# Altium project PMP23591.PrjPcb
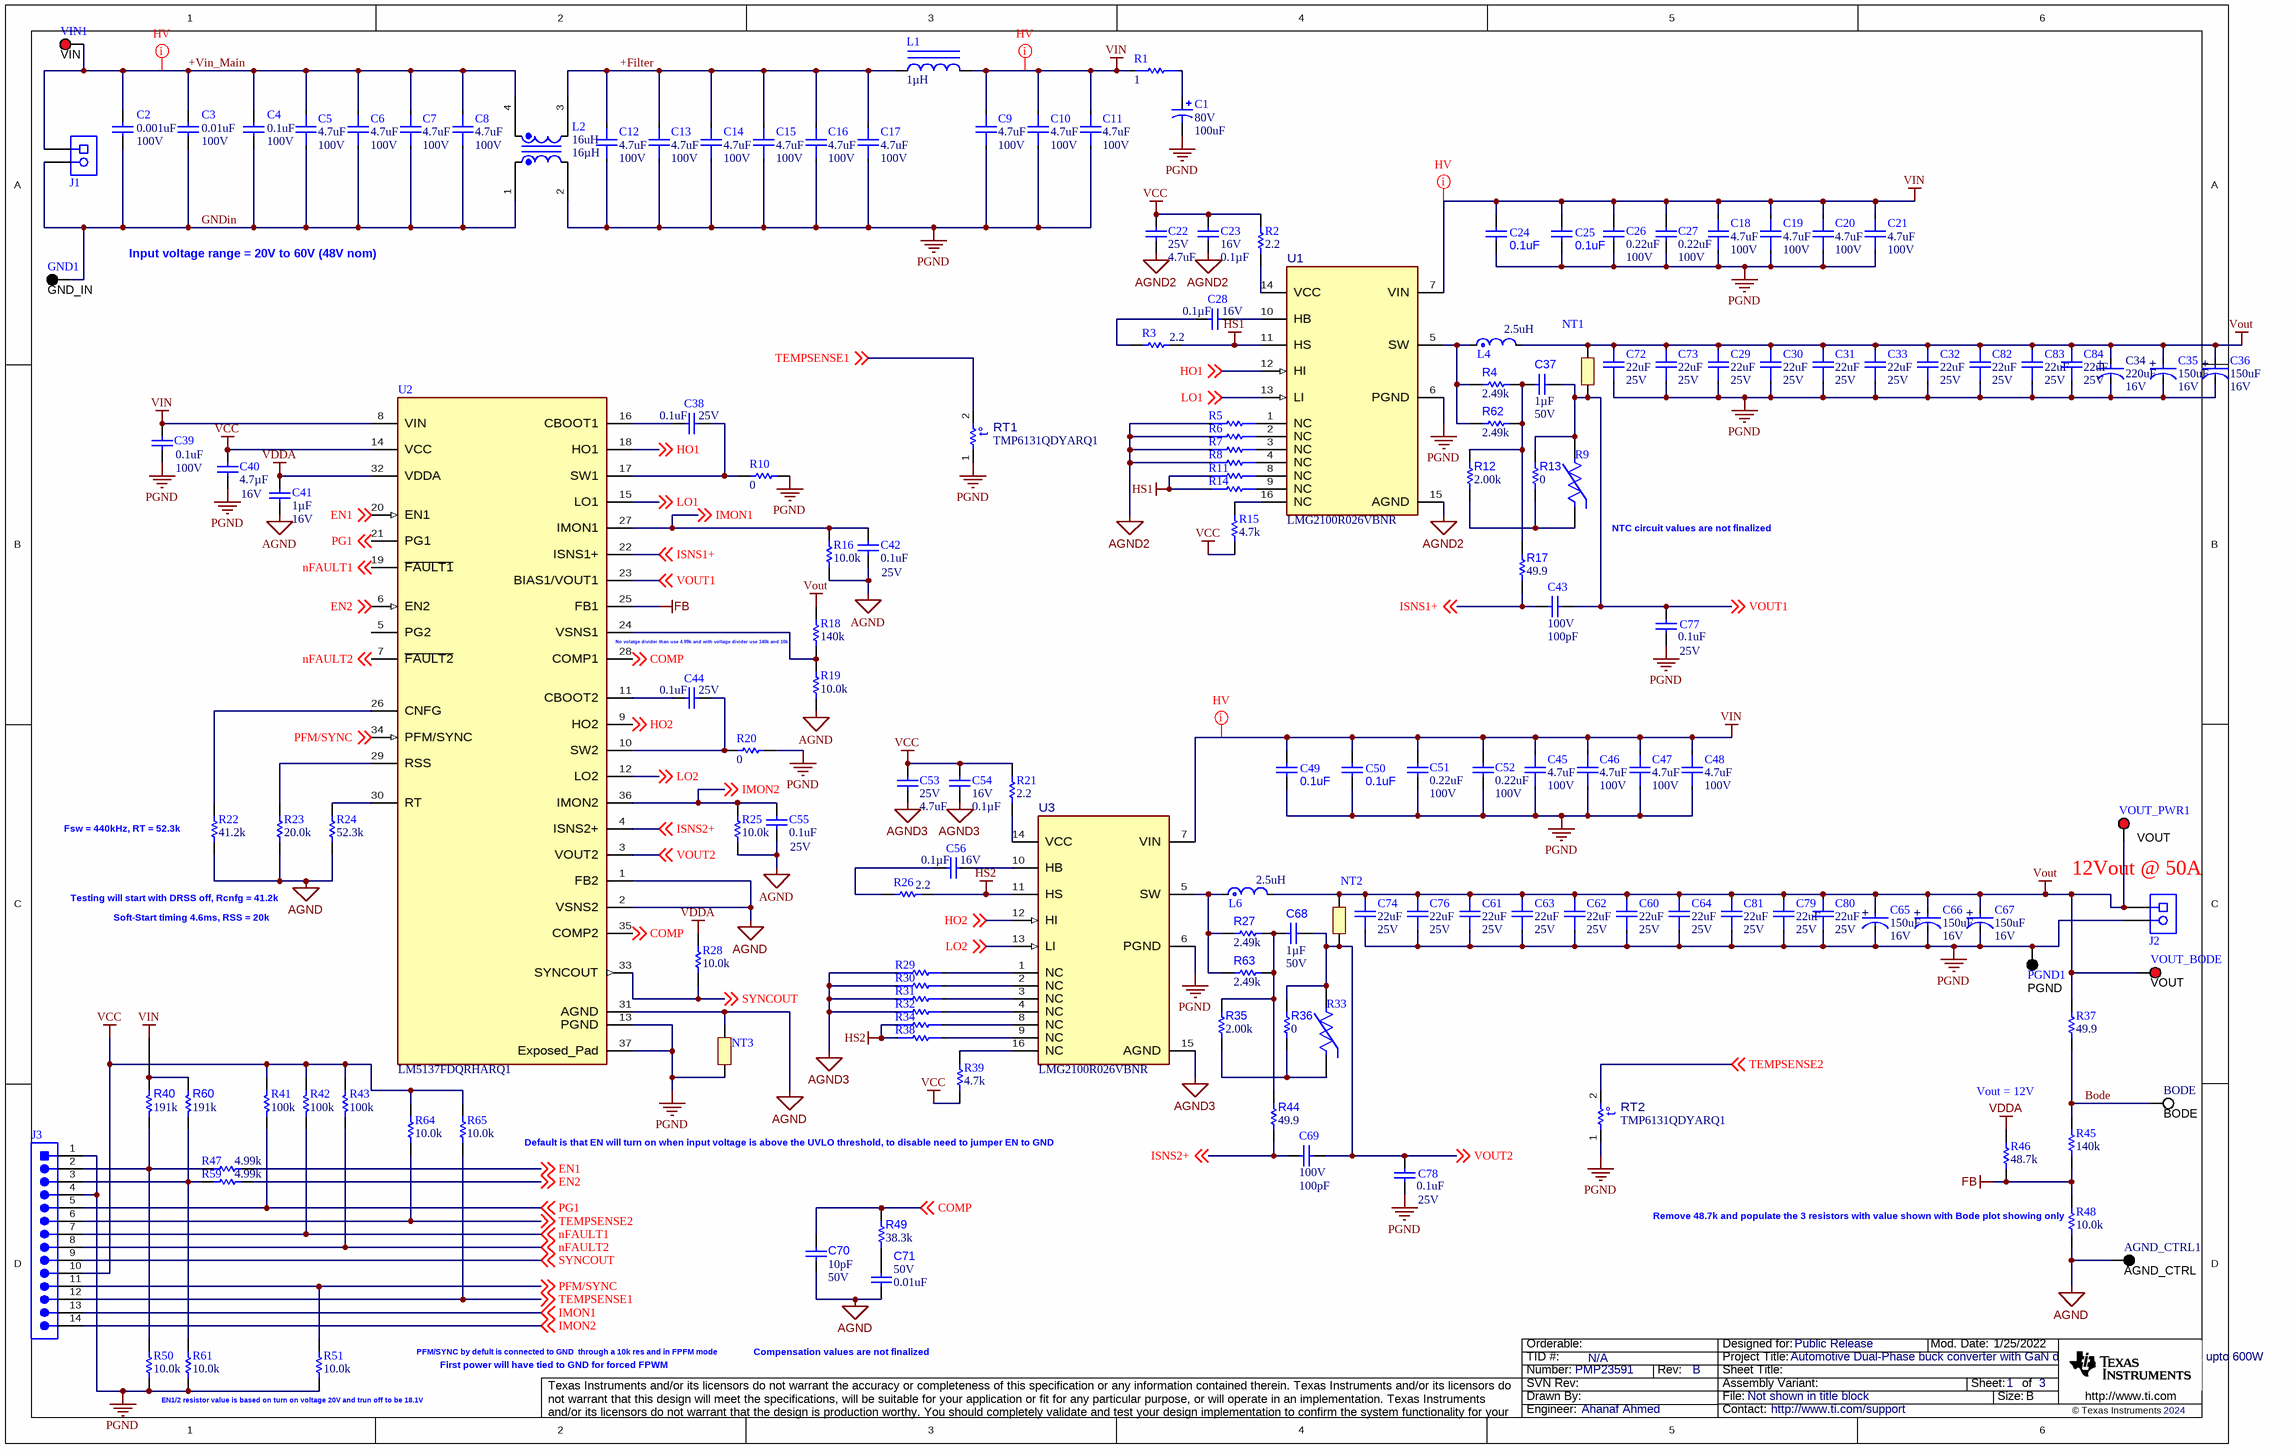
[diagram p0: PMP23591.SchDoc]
CopyrightYear: 2024; PCB_Layout: Ahanaf Ahmed; PCB_Rev: B; PRJ_Customer: Public Release; PRJ_Engineer: Ahanaf Ahmed; PRJ_Number: PMP23591; PRJ_Title: Automotive Dual-Phase buck converter with GaN device 48V input to 12V/50A upto 600W; SCH_Rev: B; TechSupport: http://www.ti.com/support; TID: N/A
3 sheets, 198 parts. Net scope: global (net labels, ports and power ports of the same name join across sheets).
Board file: PMP23591.PcbDoc
Sheets:
  PMP23591.SchDoc
  PMP23591.DynamicLoad.SchDoc
  PMP23591_Hardware.SchDoc

## Sheet PMP23591.SchDoc
size 431 x 279 mm; Date: Not shown in title block; ApprovedBy: Not shown in title block; CheckedBy: Not shown in title block; Author: Not shown in title block; CompanyName: Not shown in title block; Engineer: Not shown in title block; Organization: Not shown in title block; Address1: Not shown in title block; Address2: Not shown in title block; Address3: Not shown in title block; Address4: Not shown in title block; DocumentNumber: 1; Revision: Use project parameter SCH_Rev; SheetNumber: 1; SheetTotal: 3; PageSetup: Record=PageOptions¦CenterHorizontal=True¦CenterVertical=True¦PrintScale=1.00¦XCorrection=1.00¦YCorrection=1.00¦PrintKind=0¦BorderSize=5000000¦LeftOffset=0¦BottomOffset=0¦Orientation=2¦PaperLength=1000¦PaperWidth=1000¦Scale=100¦PaperSource=15¦PrintQuality=600¦MediaType=1¦DitherType=10¦PaperKind=Letter¦PrintScaleMode=1

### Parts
AGND_CTRL1  AGND_CTRL  [Keystone5011]
BODE  BODE  [Keystone5012]
C1  VDC_V: 80V  ValueDisplayed: 100uF  [SM_RADIAL_H13]  (hidden comment: EEV-FK1K101Q)
C2  Cap_F: 0.001uF  VDC_V: 100V  [0603]  (hidden comment: CGA3E2X7R2A102K080AA)
C3  Value2: 100V  ValueDisplayed: 0.01uF  [0603]  (hidden comment: GRM188R72A103KA01D)
C4  Value2: 100V  ValueDisplayed: 0.1uF  [0805]  (hidden comment: C0805C104K1RACTU)
C5  ValueDisplayed: 4.7uF  VDC_V: 100V  [FP-GCJ32DC72A475KE01L_1210-MFG]  (hidden comment: GCJ32DC72A475KE01L)
C6  ValueDisplayed: 4.7uF  VDC_V: 100V  [FP-GCJ32DC72A475KE01L_1210-MFG]  (hidden comment: GCJ32DC72A475KE01L)
C7  ValueDisplayed: 4.7uF  VDC_V: 100V  [FP-GCJ32DC72A475KE01L_1210-MFG]  (hidden comment: GCJ32DC72A475KE01L)
C8  ValueDisplayed: 4.7uF  VDC_V: 100V  [FP-GCJ32DC72A475KE01L_1210-MFG]  (hidden comment: GCJ32DC72A475KE01L)
C9  ValueDisplayed: 4.7uF  VDC_V: 100V  [FP-GCJ32DC72A475KE01L_1210-MFG]  (hidden comment: GCJ32DC72A475KE01L)
C10  ValueDisplayed: 4.7uF  VDC_V: 100V  [FP-GCJ32DC72A475KE01L_1210-MFG]  (hidden comment: GCJ32DC72A475KE01L)
C11  ValueDisplayed: 4.7uF  VDC_V: 100V  [FP-GCJ32DC72A475KE01L_1210-MFG]  (hidden comment: GCJ32DC72A475KE01L)
C12  ValueDisplayed: 4.7uF  VDC_V: 100V  [FP-GCJ32DC72A475KE01L_1210-MFG]  (hidden comment: GCJ32DC72A475KE01L)
C13  ValueDisplayed: 4.7uF  VDC_V: 100V  [FP-GCJ32DC72A475KE01L_1210-MFG]  (hidden comment: GCJ32DC72A475KE01L)
C14  ValueDisplayed: 4.7uF  VDC_V: 100V  [FP-GCJ32DC72A475KE01L_1210-MFG]  (hidden comment: GCJ32DC72A475KE01L)
C15  ValueDisplayed: 4.7uF  VDC_V: 100V  [FP-GCJ32DC72A475KE01L_1210-MFG]  (hidden comment: GCJ32DC72A475KE01L)
C16  ValueDisplayed: 4.7uF  VDC_V: 100V  [FP-GCJ32DC72A475KE01L_1210-MFG]  (hidden comment: GCJ32DC72A475KE01L)
C17  ValueDisplayed: 4.7uF  VDC_V: 100V  [FP-GCJ32DC72A475KE01L_1210-MFG]  (hidden comment: GCJ32DC72A475KE01L)
C18  ValueDisplayed: 4.7uF  VDC_V: 100V  [FP-GCJ32DC72A475KE01L_1210-MFG]  (hidden comment: GCJ32DC72A475KE01L)
C19  ValueDisplayed: 4.7uF  VDC_V: 100V  [FP-GCJ32DC72A475KE01L_1210-MFG]  (hidden comment: GCJ32DC72A475KE01L)
C20  ValueDisplayed: 4.7uF  VDC_V: 100V  [FP-GCJ32DC72A475KE01L_1210-MFG]  (hidden comment: GCJ32DC72A475KE01L)
C21  ValueDisplayed: 4.7uF  VDC_V: 100V  [FP-GCJ32DC72A475KE01L_1210-MFG]  (hidden comment: GCJ32DC72A475KE01L)
C22  VDC_V: 25V  ValueDisplayed: 4.7uF  [0805_HV]  (hidden comment: GCM21BC71E475KE36L)
C23  VDC_V: 16V  ValueDisplayed: 0.1µF  [0402]  (hidden comment: GCM155R71C104JA55D)
C24  ValueDisplayed: 0.1uF  [0603]  (hidden comment: CGA3E2X7R1E104K080AA)
C25  ValueDisplayed: 0.1uF  [0603]  (hidden comment: CGA3E2X7R1E104K080AA)
C26  Cap_F: 0.22uF  VDC_V: 100V  [0805]  (hidden comment: CL21B224KCFSNWE)
C27  Cap_F: 0.22uF  VDC_V: 100V  [0805]  (hidden comment: CL21B224KCFSNWE)
C28  VDC_V: 16V  ValueDisplayed: 0.1µF  [0402]  (hidden comment: GCM155R71C104JA55D)
C29  ValueDisplayed: 22uF  VDC_V: 25V  [FP-CGA6P3X7R1E226M250AB_1210-MFG]  (hidden comment: CGA6P3X7R1E226M250AB)
C30  ValueDisplayed: 22uF  VDC_V: 25V  [FP-CGA6P3X7R1E226M250AB_1210-MFG]  (hidden comment: CGA6P3X7R1E226M250AB)
C31  ValueDisplayed: 22uF  VDC_V: 25V  [FP-CGA6P3X7R1E226M250AB_1210-MFG]  (hidden comment: CGA6P3X7R1E226M250AB)
C32  ValueDisplayed: 22uF  VDC_V: 25V  [FP-CGA6P3X7R1E226M250AB_1210-MFG]  (hidden comment: CGA6P3X7R1E226M250AB)
C33  ValueDisplayed: 22uF  VDC_V: 25V  [FP-CGA6P3X7R1E226M250AB_1210-MFG]  (hidden comment: CGA6P3X7R1E226M250AB)
C34  ValueDisplayed: 220uF  VDC_V: 16V  [FP-TCME227M016R0025E_2917-MFG]  (hidden comment: TCME227M016R0025E)
C35  ValueDisplayed: 150uF  VDC_V: 16V  [FP-TCQE157M016R0025E_2917-MFG]  (hidden comment: TCQE157M016R0025E)
C36  ValueDisplayed: 150uF  VDC_V: 16V  [FP-TCQE157M016R0025E_2917-MFG]  (hidden comment: TCQE157M016R0025E)
C37  Cap_F: 1µF  VDC_V: 50V  [0603]  (hidden comment: UMK107AB7105KA-T)
C38  Value2: 25V  ValueDisplayed: 0.1uF  [0603]  (hidden comment: CGA3E2X7R1E104K080AA)
C39  Value2: 100V  ValueDisplayed: 0.1uF  [0603]  (hidden comment: GRM188R72A104KA35D)
C40  Value2: 16V  Cap_F: 4.7µF  [0603]  (hidden comment: GRM188Z71C475KE21D)
C41  Cap_F: 1µF  VDC_V: 16V  [0603L]  (hidden comment: GCM188R71C105KA64J)
C42  Value2: 25V  ValueDisplayed: 0.1uF  [0603]  (hidden comment: CGA3E2X7R1E104K080AA)
C43  VDC_V: 100V  ValueDisplayed: 100pF  [0603]  (hidden comment: GCM1885C2A101JA16D)
C44  Value2: 25V  ValueDisplayed: 0.1uF  [0603]  (hidden comment: CGA3E2X7R1E104K080AA)
C45  ValueDisplayed: 4.7uF  VDC_V: 100V  [FP-GCJ32DC72A475KE01L_1210-MFG]  (hidden comment: GCJ32DC72A475KE01L)
C46  ValueDisplayed: 4.7uF  VDC_V: 100V  [FP-GCJ32DC72A475KE01L_1210-MFG]  (hidden comment: GCJ32DC72A475KE01L)
C47  ValueDisplayed: 4.7uF  VDC_V: 100V  [FP-GCJ32DC72A475KE01L_1210-MFG]  (hidden comment: GCJ32DC72A475KE01L)
C48  ValueDisplayed: 4.7uF  VDC_V: 100V  [FP-GCJ32DC72A475KE01L_1210-MFG]  (hidden comment: GCJ32DC72A475KE01L)
C49  ValueDisplayed: 0.1uF  [0603]  (hidden comment: CGA3E2X7R1E104K080AA)
C50  ValueDisplayed: 0.1uF  [0603]  (hidden comment: CGA3E2X7R1E104K080AA)
C51  Cap_F: 0.22uF  VDC_V: 100V  [0805]  (hidden comment: CL21B224KCFSNWE)
C52  Cap_F: 0.22uF  VDC_V: 100V  [0805]  (hidden comment: CL21B224KCFSNWE)
C53  VDC_V: 25V  ValueDisplayed: 4.7uF  [0805_HV]  (hidden comment: GCM21BC71E475KE36L)
C54  VDC_V: 16V  ValueDisplayed: 0.1µF  [0402]  (hidden comment: GCM155R71C104JA55D)
C55  Value2: 25V  ValueDisplayed: 0.1uF  [0603]  (hidden comment: CGA3E2X7R1E104K080AA)
C56  VDC_V: 16V  ValueDisplayed: 0.1µF  [0402]  (hidden comment: GCM155R71C104JA55D)
C60  ValueDisplayed: 22uF  VDC_V: 25V  [FP-CGA6P3X7R1E226M250AB_1210-MFG]  (hidden comment: CGA6P3X7R1E226M250AB)
C61  ValueDisplayed: 22uF  VDC_V: 25V  [FP-CGA6P3X7R1E226M250AB_1210-MFG]  (hidden comment: CGA6P3X7R1E226M250AB)
C62  ValueDisplayed: 22uF  VDC_V: 25V  [FP-CGA6P3X7R1E226M250AB_1210-MFG]  (hidden comment: CGA6P3X7R1E226M250AB)
C63  ValueDisplayed: 22uF  VDC_V: 25V  [FP-CGA6P3X7R1E226M250AB_1210-MFG]  (hidden comment: CGA6P3X7R1E226M250AB)
C64  ValueDisplayed: 22uF  VDC_V: 25V  [FP-CGA6P3X7R1E226M250AB_1210-MFG]  (hidden comment: CGA6P3X7R1E226M250AB)
C65  ValueDisplayed: 150uF  VDC_V: 16V  [FP-TCQE157M016R0025E_2917-MFG]  (hidden comment: TCQE157M016R0025E)
C66  ValueDisplayed: 150uF  VDC_V: 16V  [FP-TCQE157M016R0025E_2917-MFG]  (hidden comment: TCQE157M016R0025E)
C67  ValueDisplayed: 150uF  VDC_V: 16V  [FP-TCQE157M016R0025E_2917-MFG]  (hidden comment: TCQE157M016R0025E)
C68  Cap_F: 1µF  VDC_V: 50V  [0603]  (hidden comment: UMK107AB7105KA-T)
C69  VDC_V: 100V  ValueDisplayed: 100pF  [0603]  (hidden comment: GCM1885C2A101JA16D)
C70  ValueDisplayed: 10pF  VDC_V: 50V  [0603]  (hidden comment: CGA3E2C0G1H100D080AA)
C71  VDC_V: 50V  ValueDisplayed: 0.01uF  [0603]  (hidden comment: GCM188R71H103KA37D)
C72  ValueDisplayed: 22uF  VDC_V: 25V  [FP-CGA6P3X7R1E226M250AB_1210-MFG]  (hidden comment: CGA6P3X7R1E226M250AB)
C73  ValueDisplayed: 22uF  VDC_V: 25V  [FP-CGA6P3X7R1E226M250AB_1210-MFG]  (hidden comment: CGA6P3X7R1E226M250AB)
C74  ValueDisplayed: 22uF  VDC_V: 25V  [FP-CGA6P3X7R1E226M250AB_1210-MFG]  (hidden comment: CGA6P3X7R1E226M250AB)
C76  ValueDisplayed: 22uF  VDC_V: 25V  [FP-CGA6P3X7R1E226M250AB_1210-MFG]  (hidden comment: CGA6P3X7R1E226M250AB)
C77  Value2: 25V  ValueDisplayed: 0.1uF  [0603]  (hidden comment: CGA3E2X7R1E104K080AA)
C78  Value2: 25V  ValueDisplayed: 0.1uF  [0603]  (hidden comment: CGA3E2X7R1E104K080AA)
C79  ValueDisplayed: 22uF  VDC_V: 25V  [FP-CGA6P3X7R1E226M250AB_1210-MFG]  (hidden comment: CGA6P3X7R1E226M250AB)
C80  ValueDisplayed: 22uF  VDC_V: 25V  [FP-CGA6P3X7R1E226M250AB_1210-MFG]  (hidden comment: CGA6P3X7R1E226M250AB)
C81  ValueDisplayed: 22uF  VDC_V: 25V  [FP-CGA6P3X7R1E226M250AB_1210-MFG]  (hidden comment: CGA6P3X7R1E226M250AB)
C82  ValueDisplayed: 22uF  VDC_V: 25V  [FP-CGA6P3X7R1E226M250AB_1210-MFG]  (hidden comment: CGA6P3X7R1E226M250AB)
C83  ValueDisplayed: 22uF  VDC_V: 25V  [FP-CGA6P3X7R1E226M250AB_1210-MFG]  (hidden comment: CGA6P3X7R1E226M250AB)
C84  ValueDisplayed: 22uF  VDC_V: 25V  [FP-CGA6P3X7R1E226M250AB_1210-MFG]  (hidden comment: CGA6P3X7R1E226M250AB)
GND1  GND_IN  [Keystone5011]
J1  EM292902-UL  [Eaton_EM292902]  (value not drawn)
J2  EM292902-UL  [Eaton_EM292902]  (value not drawn)
J3  TSW-114-07-G-S  [TSW-114-07-G-S]  (value not drawn)
L1  ValueDisplayed: 1µH  [VCHA105D]  (hidden comment: VCHA105D-1R0MS6)
L2  value 16uH  ValueDisplayed: 16µH  [WE-CMB_NiZn_S]  (hidden comment: 7448421016)
L4  value 2.5uH  [FP-VCUD128T-2R5MS8_SMT_IND_13MM3_12MM8-MFG]  (hidden comment: VCUD128T-2R5MS8)
L6  value 2.5uH  [FP-VCUD128T-2R5MS8_SMT_IND_13MM3_12MM8-MFG]
NT1  Net-Tie  [Net-Tie_10mil]  (value not drawn)  (net tie, no BOM)
NT2  Net-Tie  [Net-Tie_10mil]  (value not drawn)  (net tie, no BOM)
NT3  Net-Tie  [Net-Tie_10mil]  (value not drawn)  (net tie, no BOM)
PGND1  PGND  [Keystone5011]
R1  value 1  [FP-RCL12251R00FKEG_2512-MFG]  (hidden comment: RCL12251R00FKEG)
R2  ValueDisplayed: 2.2  [0402]  (hidden comment: CRCW04022R20JNED)
R3  ValueDisplayed: 2.2  [0402]  (hidden comment: CRCW04022R20JNED)
R4  ValueDisplayed: 2.49k  [1210]  (hidden comment: RC1210FR-072K49L)
R5  CRCW06030000Z0EAHP  [FP-CRCW06030000Z0EAHP_0603-MFG]  (value not drawn)
R6  CRCW06030000Z0EAHP  [FP-CRCW06030000Z0EAHP_0603-MFG]  (value not drawn)
R7  CRCW06030000Z0EAHP  [FP-CRCW06030000Z0EAHP_0603-MFG]  (value not drawn)
R8  CRCW06030000Z0EAHP  [FP-CRCW06030000Z0EAHP_0603-MFG]  (value not drawn)
R9  NCU18WB473J6SRB  [FP-NCU18WB473J6SRB_0603-MFG]  (value not drawn)
R10  ValueDisplayed: 0  [0603]  (hidden comment: CRCW06030000Z0EA)
R11  CRCW06030000Z0EAHP  [FP-CRCW06030000Z0EAHP_0603-MFG]  (value not drawn)
R12  ValueDisplayed: 2.00k  [0603]  (hidden comment: CRCW06032K00FKEA)
R13  ValueDisplayed: 0  [0603]  (hidden comment: RCS06030000Z0EA)
R14  CRCW06030000Z0EAHP  [FP-CRCW06030000Z0EAHP_0603-MFG]  (value not drawn)
R15  ValueDisplayed: 4.7k  [0603]  (hidden comment: CRCW06034K70JNEA)
R16  ValueDisplayed: 10.0k  [0603]  (hidden comment: CRCW060310K0FKEA)
R17  ValueDisplayed: 49.9  [0603]  (hidden comment: ERJ-3EKF49R9V)
R18  ValueDisplayed: 140k  [0603]  (hidden comment: ERA-3AEB1403V)
R19  ValueDisplayed: 10.0k  [0603L]  (hidden comment: CRCW060310K0FKEA)
R20  ValueDisplayed: 0  [0603]  (hidden comment: CRCW06030000Z0EA)
R21  ValueDisplayed: 2.2  [0402]  (hidden comment: CRCW04022R20JNED)
R22  ValueDisplayed: 41.2k  [0603]  (hidden comment: CRCW060341K2FKEA)
R23  ValueDisplayed: 20.0k  [0603S]  (hidden comment: CRCW060320K0FKEA)
R24  ValueDisplayed: 52.3k  [0603L]  (hidden comment: CRCW060352K3FKEA)
R25  ValueDisplayed: 10.0k  [0603]  (hidden comment: CRCW060310K0FKEA)
R26  ValueDisplayed: 2.2  [0402]  (hidden comment: CRCW04022R20JNED)
R27  ValueDisplayed: 2.49k  [1210]  (hidden comment: RC1210FR-072K49L)
R28  ValueDisplayed: 10.0k  [0603]  (hidden comment: CRCW060310K0FKEA)
R29  CRCW06030000Z0EAHP  [FP-CRCW06030000Z0EAHP_0603-MFG]  (value not drawn)
R30  CRCW06030000Z0EAHP  [FP-CRCW06030000Z0EAHP_0603-MFG]  (value not drawn)
R31  CRCW06030000Z0EAHP  [FP-CRCW06030000Z0EAHP_0603-MFG]  (value not drawn)
R32  CRCW06030000Z0EAHP  [FP-CRCW06030000Z0EAHP_0603-MFG]  (value not drawn)
R33  NCU18WB473J6SRB  [FP-NCU18WB473J6SRB_0603-MFG]  (value not drawn)
R34  CRCW06030000Z0EAHP  [FP-CRCW06030000Z0EAHP_0603-MFG]  (value not drawn)
R35  ValueDisplayed: 2.00k  [0603]  (hidden comment: CRCW06032K00FKEA)
R36  ValueDisplayed: 0  [0603]  (hidden comment: RCS06030000Z0EA)
R37  ValueDisplayed: 49.9  [0603L]  (hidden comment: CRCW060349R9FKEA)
R38  CRCW06030000Z0EAHP  [FP-CRCW06030000Z0EAHP_0603-MFG]  (value not drawn)
R39  ValueDisplayed: 4.7k  [0603]  (hidden comment: CRCW06034K70JNEA)
R40  ValueDisplayed: 191k  [0603]  (hidden comment: CRCW0603191KFKEA)
R41  ValueDisplayed: 100k  [0603L]  (hidden comment: CRCW0603100KFKEA)
R42  ValueDisplayed: 100k  [0603L]  (hidden comment: CRCW0603100KFKEA)
R43  ValueDisplayed: 100k  [0603L]  (hidden comment: CRCW0603100KFKEA)
R44  ValueDisplayed: 49.9  [0603]  (hidden comment: ERJ-3EKF49R9V)
R45  ValueDisplayed: 140k  [0603]  (hidden comment: ERA-3AEB1403V)
R46  ValueDisplayed: 48.7k  [0603]  (hidden comment: CRCW060348K7FKEA)
R47  ValueDisplayed: 4.99k  [0603]  (hidden comment: CRCW06034K99FKEA)
R48  ValueDisplayed: 10.0k  [0603L]  (hidden comment: CRCW060310K0FKEA)
R49  ValueDisplayed: 38.3k  [0603]  (hidden comment: CRCW060338K3FKEA)
R50  ValueDisplayed: 10.0k  [0603]  (hidden comment: CRCW060310K0FKEA)
R51  ValueDisplayed: 10.0k  [0603]  (hidden comment: CRCW060310K0FKEA)
R59  ValueDisplayed: 4.99k  [0603]  (hidden comment: CRCW06034K99FKEA)
R60  ValueDisplayed: 191k  [0603]  (hidden comment: CRCW0603191KFKEA)
R61  ValueDisplayed: 10.0k  [0603]  (hidden comment: CRCW060310K0FKEA)
R62  ValueDisplayed: 2.49k  [1210]  (hidden comment: RC1210FR-072K49L)
R63  ValueDisplayed: 2.49k  [1210]  (hidden comment: RC1210FR-072K49L)
R64  ValueDisplayed: 10.0k  [0603]  (hidden comment: CRCW060310K0FKEA)
R65  ValueDisplayed: 10.0k  [0603]  (hidden comment: CRCW060310K0FKEA)
RT1  TMP6131QDYARQ1  [DYA0002A-MFG]
RT2  TMP6131QDYARQ1  [DYA0002A-MFG]
U1  LMG2100R026VBNR  [VBN0016A-MFG]
U2  LM5137FDQRHARQ1  [RHA0036D-MFG]
U3  LMG2100R026VBNR  [VBN0016A-MFG]
VIN1  VIN  [Keystone5010]
VOUT_BODE  VOUT  [Keystone5010]
VOUT_PWR1  VOUT  [Keystone5010]

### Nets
AGND: AGND_CTRL1.1 C41.1 C42.1 C55.1 C70.2 C71.2 NT3.2 R16.2 R19.2 R22.1 R23.1 R24.1 R25.2 R48.2 U2.1(FB2) U2.2(VSNS2) U2.31(AGND)
AGND2: C22.2 C23.2 R5.1 R6.1 R7.1 R8.1 U1.15(AGND)
AGND3: C53.2 C54.2 R29.1 R30.1 R31.1 R32.1 U3.15(AGND)
FB: R45.1 R46.1 R48.1 U2.25(FB1)
HS1: R3.1 R11.1 R14.1 U1.11(HS)
HS2: R26.1 R34.1 R38.1 U3.11(HS)
PGND: C1.2(-) C9.1 C10.1 C11.1 C12.1 C13.1 C14.1 C15.1 C16.1 C17.1 C18.1 C19.1 C20.1 C21.1 C24.1 C25.1 C26.2 C27.2 C29.1 C30.1 C31.1 C32.1 C33.1 C34.1(CATHODE) C35.1(CATHODE) C36.1(CATHODE) C39.2 C40.2 C45.1 C46.1 C47.1 C48.1 C49.1 C50.1 C51.2 C52.2 C60.1 C61.1 C62.1 C63.1 C64.1 C65.1(CATHODE) C66.1(CATHODE) C67.1(CATHODE) C72.1 C73.1 C74.1 C76.1 C77.1 C78.1 C79.1 C80.1 C81.1 C82.1 C83.1 C84.1 J2.2 J3.1 J3.4 L2.2 NT3.1 PGND1.1 R10.2 R20.2 R50.2 R51.2 R61.2 RT1.1 RT2.1 U1.6(PGND) U2.13(PGND) U2.37(Exposed_Pad) U3.6(PGND)
VCC: C22.1 C23.1 C40.1 C53.1 C54.1 J3.10 R2.1 R15.2 R21.1 R39.2 R41.2 R42.2 R43.2 R64.1 R65.1 U2.14(VCC)
VDDA: C41.2 R28.1 R46.2 U2.32(VDDA)
VIN: C9.2 C10.2 C11.2 C18.2 C19.2 C20.2 C21.2 C24.2 C25.2 C26.1 C27.1 C39.1 C45.2 C46.2 C47.2 C48.2 C49.2 C50.2 C51.1 C52.1 L1.2 R1.2 R40.2 R60.2 U1.7(VIN) U2.8(VIN) U3.7(VIN)
Vout: C29.2 C30.2 C31.2 C32.2 C33.2 C34.2(ANODE) C35.2(ANODE) C36.2(ANODE) C60.2 C61.2 C62.2 C63.2 C64.2 C65.2(ANODE) C66.2(ANODE) C67.2(ANODE) C72.2 C73.2 C74.2 C76.2 C79.2 C80.2 C81.2 C82.2 C83.2 C84.2 J2.1 L4.2 L6.2 NT1.2 NT2.2 R18.2 R37.2 VOUT_BODE.1 VOUT_PWR1.1
+Filter: C12.2 C13.2 C14.2 C15.2 C16.2 C17.2 L1.1 L2.3
+Vin_Main: C2.1 C3.2 C4.1 C5.2 C6.2 C7.2 C8.2 J1.1 L2.4 VIN1.1
Bode: BODE.1 R37.1 R45.2
COMP: C70.1 R49.2 U2.28(COMP1) U2.35(COMP2) ; off-sheet COMP
EN1: R47.2 U2.20(EN1) ; off-sheet EN1
EN2: R59.2 U2.6(EN2) ; off-sheet EN2
GNDin: C2.2 C3.1 C4.2 C5.1 C6.1 C7.1 C8.1 GND1.1 J1.2 L2.1
HO1: U1.12(HI) U2.18(HO1) ; off-sheet HO1
HO2: U2.9(HO2) U3.12(HI) ; off-sheet HO2
IMON1: C42.2 J3.13 R16.1 U2.27(IMON1) ; off-sheet IMON1
IMON2: C55.2 J3.14 R25.1 U2.36(IMON2) ; off-sheet IMON2
ISNS1+: C43.2 R17.1 U2.22(ISNS1+) ; off-sheet ISNS1+
ISNS2+: C69.2 R44.1 U2.4(ISNS2+) ; off-sheet ISNS2+
LO1: U1.13(LI) U2.15(LO1) ; off-sheet LO1
LO2: U2.12(LO2) U3.13(LI) ; off-sheet LO2
nFAULT1: J3.7 R42.1 U2.19(~{FAULT1}) ; off-sheet nFAULT1
nFAULT2: J3.8 R43.1 U2.7(~{FAULT2}) ; off-sheet nFAULT2
PFM/SYNC: J3.11 R51.1 U2.34(PFM/SYNC) ; off-sheet PFM/SYNC
PG1: J3.5 R41.1 U2.21(PG1) ; off-sheet PG1
SYNCOUT: J3.9 R28.2 U2.33(SYNCOUT) ; off-sheet SYNCOUT
TEMPSENSE1: J3.12 R65.2 RT1.2 ; off-sheet TEMPSENSE1
TEMPSENSE2: J3.6 R64.2 RT2.2 ; off-sheet TEMPSENSE2
VOUT1: C37.1 C43.1 C77.2 NT1.1 R9.2 R13.2 U2.23(BIAS1/VOUT1) ; off-sheet VOUT1
VOUT2: C68.1 C69.1 C78.2 NT2.1 R33.2 R36.2 U2.3(VOUT2) ; off-sheet VOUT2
NetC1_1: C1.1(+) R1.1
NetC28_1: C28.1 R3.2
NetC28_2: C28.2 U1.10(HB)
NetC37_2: C37.2 R4.2 R12.2 R17.2 R62.2
NetC38_1: C38.1 R10.1 U2.17(SW1)
NetC38_2: C38.2 U2.16(CBOOT1)
NetC44_1: C44.1 R20.1 U2.10(SW2)
NetC44_2: C44.2 U2.11(CBOOT2)
NetC56_1: C56.1 R26.2
NetC56_2: C56.2 U3.10(HB)
NetC68_2: C68.2 R27.2 R35.2 R44.2 R63.2
NetC71_1: C71.1 R49.1
NetJ3_2: J3.2 R40.1 R47.1 R50.1
NetJ3_3: J3.3 R59.1 R60.1 R61.1
NetL4_1: L4.1 R4.1 R62.1 U1.5(SW)
NetL6_1: L6.1 R27.1 R63.1 U3.5(SW)
NetR2_2: R2.2 U1.14(VCC)
NetR5_2: R5.2 U1.1(NC)
NetR6_2: R6.2 U1.2(NC)
NetR7_2: R7.2 U1.3(NC)
NetR8_2: R8.2 U1.4(NC)
NetR9_1: R9.1 R12.1 R13.1
NetR11_2: R11.2 U1.8(NC)
NetR14_2: R14.2 U1.9(NC)
NetR15_1: R15.1 U1.16(NC)
NetR18_1: R18.1 R19.1 U2.24(VSNS1)
NetR21_2: R21.2 U3.14(VCC)
NetR22_2: R22.2 U2.26(CNFG)
NetR23_2: R23.2 U2.29(RSS)
NetR24_2: R24.2 U2.30(RT)
NetR29_2: R29.2 U3.1(NC)
NetR30_2: R30.2 U3.2(NC)
NetR31_2: R31.2 U3.3(NC)
NetR32_2: R32.2 U3.4(NC)
NetR33_1: R33.1 R35.1 R36.1
NetR34_2: R34.2 U3.8(NC)
NetR38_2: R38.2 U3.9(NC)
NetR39_1: R39.1 U3.16(NC)

Not connected (* = marked no-connect by the designer): U2 5(PG2)

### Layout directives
net class HV: +Vin_Main, VIN

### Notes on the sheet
- Input voltage range = 20V to 60V (48V nom)
- (near R9) NTC circuit values are not finalized
- (near U2) No volatge divider than use 4.99k and with voltage divider use 140k and 10k
- (near R22) Fsw = 440kHz, RT = 52.3k
- 12Vout @ 50A
- Testing will start with DRSS off, Rcnfg = 41.2k
- Soft-Start timing 4.6ms, RSS = 20k
- Default is that EN will turn on when input voltage is above the UVLO threshold, to disable need to jumper EN to GND
- Vout = 12V
- (near R48) Remove 48.7k and populate the 3 resistors with value shown with Bode plot showing only
- EN1/2 resistor value is based on turn on voltage 20V and trun off to be 18.1V
- First power will have tied to GND for forced FPWM
- PFM/SYNC by defult is connected to GND  through a 10k res and in FPFM mode
- Compensation values are not finalized

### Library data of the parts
AGND_CTRL1 = CMP-0055148-2: Test Point, Multipurpose, Black, TH; Manufacturer: Keystone Electronics; CNHeader: FALSE; ContactFinish: Silver; Green_REACh: Passed; Green_Lifecycle: Active; CT: TRUE
BODE = CMP-0055149-2: Test Point, Multipurpose, White, TH; Manufacturer: Keystone Electronics; ContactFinish: Silver; CT: TRUE; CNHeader: FALSE; Green_Lifecycle: Active; Green_REACh: Passed
C1 = CMP-0011216-2: CAP, AL, 100 uF, 80 V, +/- 20%, 0.32 ohm, AEC-Q200 Grade 2, SMD; Manufacturer: Panasonic; TaMin_C: -55°C; ESR_ohm: 0.32; Polarized: Y; SizeAreaWB_mm2: 263.5; U/M: EA; Value: 100uF; TaMax_C: 105°C; SizeZ_mm: 13.5; SizeX_mm: 15; Cap_Case: H13; SizeArea_mm2: 202.5; CompType: Capacitor; Cap_F: 100µF; IRMS_A: 500mA; AEC Grade: 2; AEC Category: Q200
C2 = CMP-0007081-4: CAP, CERM, 1000 pF, 100 V, +/- 10%, X7R, AEC-Q200 Grade 1, 0603; Manufacturer: TDK; TaMin_C: -55°C; ESR_ohm: 1.9714; Polarized: N; SizeAreaWB_mm2: 4.68; Value1: 1.97137 ohm; U/M: EA; Value: 1000pF; TaMax_C: 125°C; SizeZ_mm: 1; SizeX_mm: 1.6; SizeY_mm: 0.8; SizeArea_mm2: 1.28; AEC Qualified: Y; IRMS_A: 305.705mA; AEC Category: Q200
C3 = CMP-0007468-5: CAP, CERM, 0.01 uF, 100 V, +/- 10%, X7R, 0603; Manufacturer: MuRata; TaMin_C: -55°C; Polarized: N; SizeAreaWB_mm2: 4.68; Value1: Unknown; U/M: EA; Value: 0.01uF; TaMax_C: 125°C; SizeZ_mm: 1; SizeX_mm: 1.6; SizeY_mm: 0.8; SizeArea_mm2: 1.28; Cap_F: 10nF; AEC Category: Q200
C4 = CMP-0007722-2: CAP, CERM, 0.1 uF, 100 V, +/- 10%, X7R, 0805; Manufacturer: Kemet; TaMin_C: -55°C; ESR_ohm: 64m; Polarized: N; SizeAreaWB_mm2: 6.75; Value1: 0.064 ohm; U/M: EA; Value: 0.1uF; TaMax_C: 125°C; SizeZ_mm: 1.45; SizeX_mm: 2; SizeY_mm: 1.25; SizeArea_mm2: 2.5; Cap_F: 100nF; IRMS_A: 1.64A; AEC Category: Q200
C5-C21 C45-C48 = CMP-0093675-1: 4.7uF ±10% 100V Ceramic Capacitor X7S 1210 (3225 Metric); Manufacturer: Murata; Value: 4.7µF; AEC Qualified: Yes; TempCo: 22%; SizeZ_mm: 2.3mm; AEC Grade: Grade 1
C22 C53 = CMP-0008013-2: CAP, CERM, 4.7 uF, 25 V, +/- 10%, X7S, AEC-Q200 Grade 1, 0805; Manufacturer: MuRata; TaMin_C: -55°C; Polarized: N; SizeAreaWB_mm2: 6.75; Value1: Unknown; U/M: EA; Value: 4.7uF; TaMax_C: 125°C; SizeZ_mm: 1.45; SizeX_mm: 2; SizeY_mm: 1.25; Cap_Case: 0805; SizeArea_mm2: 2.5; AEC Qualified: Y; Cap_F: 4.7µF; AEC Grade: 1; AEC Category: Q200
C23 C28 C54 C56 = CMP-0080702-1: CAP, CERM, 0.1 µF, 16 V,+/- 5%, X7R, AEC-Q200 Grade 1, 0402; Manufacturer: MuRata; Cap_F: 100nF; SizeAreaWB_mm2: 3; SizeArea_mm2: 0.5; AEC Qualified: Y; AEC Category: Q200; Value: 0.1uF; TaMax_C: 125°C; SizeZ_mm: 0.6; AEC Grade: 1; Polarized: N; TaMin_C: -55°C; U/M: EA
C24 C25 C49 C50 = CMP-0007077-5: CAP, CERM, 0.1 uF, 25 V, +/- 10%, X7R, AEC-Q200 Grade 1, 0603; Manufacturer: TDK; TaMin_C: -55°C; Polarized: N; SizeAreaWB_mm2: 4.68; Value1: Unknown; U/M: EA; Value: 0.1uF; TaMax_C: 125°C; SizeZ_mm: 1; SizeX_mm: 1.6; SizeY_mm: 0.8; Value2: 25V; SizeArea_mm2: 1.28; AEC Qualified: Y; Cap_F: 100nF; AEC Category: Q200
C26 C27 C51 C52 = CMP-0007996-2: CAP, CERM, 0.22 uF, 100 V, +/- 10%, X7R, 0805; Manufacturer: Samsung Electro-Mechanics; TaMin_C: -55°C; Polarized: N; SizeAreaWB_mm2: 6.75; Value1: Unknown; U/M: EA; Value: 0.22uF; TaMax_C: 125°C; SizeZ_mm: 1.45; SizeX_mm: 2; SizeY_mm: 1.25; SizeArea_mm2: 2.5; AEC Category: Q200
C29-C33 C60-C64 C72-C74 C76 C79-C84 = CMP-0036912-1: Cap Ceramic 22uF 25V X7R 20% Pad SMD 1210 +125°C Automotive T/R; Manufacturer: TDK; AEC Grade: Grade 1; AEC Qualified: Yes; Cap_F: 22µF; SizeZ_mm: 2.8mm; TempCo: 15%; Tolerance_%: 0.2%; Value: 22µF
C34 = CMP-0092618-1: Cap Tant Polymer 220uF 16VDC E CASE 20% (7.3 X 4.3 X 4.1mm) SMD 7343-43 0.025 Ohm 125C T/R; Manufacturer: AVX; AEC Qualified: No; Cap_F: 220µF; IRMS_A: 4A; SizeZ_mm: 4.3mm; Dissipation Factor: 8%; Esr: 25m; Leakage Current: 352uA; Life: 2000Hours; Value: 220µF
C35 C36 C65-C67 = CMP-0124500-1: Cap Tant Polymer 150uF 16VDC E CASE 20%( 7.3 X 4.3 X 4.1mm) J Lead SMD 7343-43 0.025 Ohm 125C T/R; Manufacturer: KYOCERA AVX; AEC Grade: Grade 1; AEC Qualified: Yes; Cap_F: 150µF; IRMS_A: 3.162A; SizeZ_mm: 4.3mm; Dissipation Factor: 8%; Esr: 25m; Leakage Current: 240uA; Life: 2000Hours; Value: 150µF
C37 C68 = CMP-0007508-5: CAP, CERM, 1 uF, 50 V, +/- 10%, X7R, 0603; Manufacturer: Taiyo Yuden; SizeAreaWB_mm2: 4.68; SizeArea_mm2: 1.28; AEC Category: Q200; Value: 1uF; TaMax_C: 125°C; SizeZ_mm: 1; Polarized: N; TaMin_C: -55°C; SizeY_mm: 0.8; U/M: EA; SizeX_mm: 1.6; Value1: Unknown
C38 C42 C44 C55 C77 C78 = CMP-0007077-5: CAP, CERM, 0.1 uF, 25 V, +/- 10%, X7R, AEC-Q200 Grade 1, 0603; Manufacturer: TDK; TaMin_C: -55°C; Polarized: N; SizeAreaWB_mm2: 4.68; Value1: Unknown; U/M: EA; Value: 0.1uF; TaMax_C: 125°C; SizeZ_mm: 1; SizeX_mm: 1.6; SizeY_mm: 0.8; SizeArea_mm2: 1.28; AEC Qualified: Y; Cap_F: 100nF; AEC Category: Q200
C39 = CMP-0007469-4: CAP, CERM, 0.1 uF, 100 V, +/- 10%, X7R, 0603; Manufacturer: MuRata; TaMin_C: -55°C; Polarized: N; SizeAreaWB_mm2: 4.68; Value1: Unknown; U/M: EA; Value: 0.1uF; TaMax_C: 125°C; SizeZ_mm: 1; SizeX_mm: 1.6; SizeY_mm: 0.8; SizeArea_mm2: 1.28; Cap_F: 100nF; AEC Category: Q200
C40 = CMP-0064936-4: CAP, CERM, 4.7 uF, 16 V,+/- 10%, X7R, 0603; Manufacturer: MuRata; TaMin_C: -55°C; Polarized: N; SizeAreaWB_mm2: 4.68; Value1: Unknown; U/M: EA; Value: 4.7uF; TaMax_C: 125°C; SizeZ_mm: 1; SizeX_mm: 1.6; SizeY_mm: 0.8; SizeArea_mm2: 1.28; AEC Category: Q200
C41 = CMP-0079154-1: CAP, CERM, 1 µF, 16 V,+/- 10%, X7R, AEC-Q200 Grade 1, 0603; Manufacturer: MuRata; SizeAreaWB_mm2: 4.68; SizeArea_mm2: 1.28; AEC Qualified: Y; AEC Category: Q200; Value: 1uF; TaMax_C: 125°C; SizeZ_mm: 1; Polarized: N; TaMin_C: -55°C; SizeY_mm: 0.8; U/M: EA; SizeX_mm: 1.6; Cap_Case: 0603
C43 C69 = CMP-0007130-4: CAP, CERM, 100 pF, 100 V, +/- 5%, C0G/NP0, AEC-Q200 Grade 1, 0603; Manufacturer: MuRata; TaMin_C: -55°C; Polarized: N; SizeAreaWB_mm2: 4.68; Value1: Unknown; U/M: EA; TaMax_C: 125°C; SizeZ_mm: 1; SizeX_mm: 1.6; SizeY_mm: 0.8; SizeArea_mm2: 1.28; AEC Qualified: Y; AEC Category: Q200; Value: 100pF
C70 = CMP-0007069-4: CAP, CERM, 10 pF, 50 V, +/- 5%, C0G/NP0, AEC-Q200 Grade 1, 0603; Manufacturer: TDK; TaMax_C: 125°C; AEC Category: Q200; AEC Grade: 1; TaMin_C: -55°C; SizeArea_mm2: 1.28; Value: 10pF; AEC Qualified: Y; Polarized: N; SizeX_mm: 1.6; U/M: EA; SizeY_mm: 0.8; SizeAreaWB_mm2: 4.68; Value1: Unknown
C71 = CMP-0007143-4: CAP, CERM, 0.01 uF, 50 V, +/- 10%, X7R, AEC-Q200 Grade 1, 0603; Manufacturer: MuRata; SizeZ_mm: 1; Value: 0.01uF; Cap_F: 10nF; AEC Qualified: Y; TaMin_C: -55°C; Polarized: N; SizeAreaWB_mm2: 4.68; Value1: Unknown; U/M: EA; TaMax_C: 125°C; SizeX_mm: 1.6; SizeY_mm: 0.8; SizeArea_mm2: 1.28; AEC Category: Q200
GND1 PGND1 = CMP-0055148-1: Test Point, Multipurpose, Black, TH; Manufacturer: Keystone; CNHeader: FALSE; Green_Lifecycle: Active; Green_REACh: Passed; ContactFinish: Silver; CT: TRUE
J1 J2 = CMP-0077513-2: Terminal Block, 10.16mm, 2x1, Tin, R/A, TH; Manufacturer: Eaton; Pitch_mm: 10.16; Gender: Female; Voltage_V: 300V; Current_A: 65A; Cert_CULUS: Y; Row_Count: 1
J3 = CMP-0075428-1: Header, 100mil, 14x1, Gold, TH; Manufacturer: Samtec; Pitch_mm: 2.54; Cert_VDE: N; Gender: Male; Cert_CSA: Y; Voltage_V: 550V; Green_REACh: Passed; Current_A: 6.3A; CT: False; Green_Lifecycle: Active; Row_Count: 1; CNHeader: True
L1 = CMP-0086238-1: Inductor, 1 µH, 30 A, 0.00276 ohm, AEC-Q200 Grade 0, SMD; Manufacturer: Cyntec; AEC Category: Q200; AEC Grade: 0; Value: 1uH; AEC Qualified: Y; Irms: 30A @ 40C rise; Isat: 37A @ 30% inductance drop; DCR_ohm: 2.76m; SizeX_mm: 10.85; Imax_A: 30A; SizeArea_mm2: 108.5; SizeZ_mm: 5.4; SizeAreaWB_mm2: 154.2; SizeY_mm: 10
L2 = CMP-0084205-1: Coupled inductor, 16 µH, 0.0027 ohm, TH; Manufacturer: Wurth Elektronik; AEC Category: Q200; AEC Qualified: N; DCR_ohm: 2.7m
L4 = CMP-0047844-1: Power Choke Coil 2.5uH 20% 100kHz 2.53mOhm 32A AECQ200 13.3x12.8x8.0mm SMT; Manufacturer: CYNTEC; AEC Grade: Grade 0; AEC Qualified: Yes; DCR_ohm: 2.53m; Ind_H: 2.5µH; Isat: 30A; Material: Metal Dust; SizeZ_mm: 8mm
L6 = CMP-0047844-1: Power Choke Coil 2.5uH 20% 100kHz 2.53mOhm 32A AECQ200 13.3x12.8x8.0mm SMT; Manufacturer: CYNTEC; PartNumber: VCUD128T-2R5MS8; AEC Grade: Grade 0; AEC Qualified: Yes; DCR_ohm: 2.53m; Ind_H: 2.5µH; Isat: 30A; Material: Metal Dust; SizeZ_mm: 8mm
NT1-NT3 = CMP-0078142-6: Single point connection between nets.
R1 = CMP-0084352-2: 1 Ohms ±1% 2W Chip Resistor Wide 2512 (6432 Metric), 1225 Automotive AEC-Q200 Thick Film; Manufacturer: Vishay Dale; SizeZ_mm: 0.8mm; Symbol Name: SYM-RCL12251R00FKEG; TempCo: 100ppm/°C; VDC_V: 200V; AEC Qualified: Yes; AEC Grade: Grade 0
R2 R3 R21 R26 = CMP-0026898-3: RES, 2.2, 5%, 0.063 W, AEC-Q200 Grade 0, 0402; Manufacturer: Vishay-Dale; Power_W: 63mW; TempCo: 200 ppm/C; Value_Code: 2R20; Value: 2.2; EIA_Code: E24; SizeX_mm: 1; SizeY_mm: 0.5; SizeZ_mm: 0.6; Value2: 0.063W; AEC Qualified: Y; VDC_V: 50V; AEC Category: Q200; AEC Grade: 0
R4 R27 R62 R63 = CMP-0083024-1: RES, 2.49 k, 1%, 0.5 W, 1210; Manufacturer: Yageo; Power_W: 500mW; TempCo: 100 ppm/C; Value_Code: 2k49; Value: 2.49k; EIA_Code: E96; SizeX_mm: 3.2; SizeY_mm: 2.5; SizeZ_mm: 1.35; Value2: 0.5W; SizeArea_mm2: 8; AEC Qualified: N; VDC_V: 200V; AEC Category: Q200; SizeAreaWB_mm2: 14.7
R5-R8 R11 R14 R29-R32 R34 R38 = CMP-0122893-1: RES Thick Film, 0Ω, , 0.33W, , 0603; Manufacturer: Vishay; AEC Grade: Grade 0; AEC Qualified: Yes; Power_W: 330mW; Res_ohm: 0; SizeZ_mm: 0.55mm; VDC_V: 75V; Power: 250mW; Value: 0
R9 R33 = CMP-0095715-1: NTC Thermistor for Temperature Sensor, Automotive, 0603, 47kΩ, 5%, 0.046mA, 5V; Manufacturer: Murata; B 25 50: 4050K; B 25 100: 4131K; SizeZ_mm: 0.95mm; AEC Qualified: Yes; B 25 85: 4108K; B Tolerance: 1%; Automotive Grade: Grade 0
R10 R20 = CMP-0025697-4: RES, 0, 5%, 0.1 W, AEC-Q200 Grade 0, 0603; Manufacturer: Vishay-Dale; Power_W: 100mW; TempCo: 200 ppm/C; Value_Code: 0000; Value: 0; EIA_Code: E24; SizeX_mm: 1.6; SizeY_mm: 0.8; SizeZ_mm: 1; Value2: 0.1W; SizeArea_mm2: 1.28; AEC Qualified: Y; VDC_V: 75V; AEC Category: Q200
R12 R35 = CMP-0022268-4: RES, 2.00 k, 1%, 0.1 W, AEC-Q200 Grade 0, 0603; Manufacturer: Vishay-Dale; Power_W: 100mW; TempCo: 100 ppm/C; Value_Code: 2k00; Value: 2.00k; EIA_Code: E96; Res_ohm: 2k; SizeX_mm: 1.6; SizeY_mm: 0.8; SizeZ_mm: 1; Value2: 0.1W; SizeArea_mm2: 1.28; AEC Qualified: Y; VDC_V: 75V; AEC Category: Q200; AEC Grade: 0
R13 R36 = CMP-0081973-1: RES, 0, 0%, 0.25 W, AEC-Q200 Grade 0, 0603; Manufacturer: Vishay-Dale; Power_W: 250mW; Value: 0; SizeX_mm: 1.6; SizeY_mm: 0.8; SizeZ_mm: 1; Value2: 0.25W; SizeArea_mm2: 1.28; AEC Qualified: Y; AEC Category: Q200; SizeAreaWB_mm2: 4.68
R15 R39 = CMP-0025817-4: RES, 4.7 k, 5%, 0.1 W, AEC-Q200 Grade 0, 0603; Manufacturer: Vishay-Dale; Power_W: 100mW; TempCo: 200 ppm/C; Value_Code: 4k70; Value: 4.7k; EIA_Code: E24; SizeX_mm: 1.6; SizeY_mm: 0.8; SizeZ_mm: 1; Value2: 0.1W; SizeArea_mm2: 1.28; AEC Qualified: Y; VDC_V: 75V; AEC Category: Q200; AEC Grade: 0
R16 R19 R25 R28 R48 R50 R51 R61 R64 R65 = CMP-0021998-4: RES, 10.0 k, 1%, 0.1 W, AEC-Q200 Grade 0, 0603; Manufacturer: Vishay-Dale; Power_W: 100mW; TempCo: 100 ppm/C; Value_Code: 10k0; Value: 10.0k; EIA_Code: E96; Res_ohm: 10k; SizeX_mm: 1.6; SizeY_mm: 0.8; SizeZ_mm: 1; Value2: 0.1W; SizeArea_mm2: 1.28; AEC Qualified: Y; VDC_V: 75V; AEC Category: Q200; AEC Grade: 0
R17 R44 = CMP-0022707-2: RES, 49.9, 1%, 0.1 W, AEC-Q200 Grade 0, 0603; Manufacturer: Panasonic; Power_W: 100mW; TempCo: 100 ppm/C; Value_Code: 49R9; Value: 49.9; EIA_Code: E96; SizeX_mm: 1.6; SizeY_mm: 0.8; SizeZ_mm: 1; Value2: 0.1W; SizeArea_mm2: 1.28; AEC Qualified: Y; AEC Category: Q200; AEC Grade: 0; U/M: EA
R18 R45 = CMP-0079245-1: RES, 140 k, 0.1%, 0.1 W, AEC-Q200 Grade 0, 0603; Manufacturer: Panasonic; SizeAreaWB_mm2: 4.68; SizeArea_mm2: 1.28; AEC Qualified: Y; AEC Category: Q200; Value: 140k; SizeZ_mm: 1; EIA_Code: E192; TempCo: 25 ppm/C; AEC Grade: 0; Power_W: 100mW; SizeY_mm: 0.8; Value2: 0.1W; SizeX_mm: 1.6
R22 = CMP-0022414-4: RES, 41.2 k, 1%, 0.1 W, AEC-Q200 Grade 0, 0603; Manufacturer: Vishay-Dale; Power_W: 100mW; TempCo: 100 ppm/C; Value_Code: 41k2; Value: 41.2k; EIA_Code: E96; SizeX_mm: 1.6; SizeY_mm: 0.8; SizeZ_mm: 1; Value2: 0.1W; SizeArea_mm2: 1.28; AEC Qualified: Y; VDC_V: 75V; AEC Category: Q200; AEC Grade: 0
R23 = CMP-0022204-4: RES, 20.0 k, 1%, 0.1 W, AEC-Q200 Grade 0, 0603; Manufacturer: Vishay-Dale; Power_W: 100mW; TempCo: 100 ppm/C; Value_Code: 20k0; Value: 20.0k; EIA_Code: E96; Res_ohm: 20k; SizeX_mm: 1.6; SizeY_mm: 0.8; SizeZ_mm: 1; Value2: 0.1W; SizeArea_mm2: 1.28; AEC Qualified: Y; VDC_V: 75V; AEC Category: Q200; AEC Grade: 0
R24 = CMP-0022486-4: RES, 52.3 k, 1%, 0.1 W, AEC-Q200 Grade 0, 0603; Manufacturer: Vishay-Dale; Power_W: 100mW; TempCo: 100 ppm/C; Value_Code: 52k3; Value: 52.3k; EIA_Code: E96; SizeX_mm: 1.6; SizeY_mm: 0.8; SizeZ_mm: 1; Value2: 0.1W; SizeArea_mm2: 1.28; AEC Qualified: Y; VDC_V: 75V; AEC Category: Q200; AEC Grade: 0
R37 = CMP-0022448-4: RES, 49.9, 1%, 0.1 W, AEC-Q200 Grade 0, 0603; Manufacturer: Vishay-Dale; Value: 49.9; Value_Code: 49R9; Power_W: 100mW; Value2: 0.1W; VDC_V: 75V; TempCo: 100 ppm/C; EIA_Code: E96; AEC Category: Q200; AEC Grade: 0; AEC Qualified: Y; SizeArea_mm2: 1.28; SizeX_mm: 1.6; SizeY_mm: 0.8; SizeZ_mm: 1
R40 R60 = CMP-0022101-4: RES, 191 k, 1%, 0.1 W, AEC-Q200 Grade 0, 0603; Manufacturer: Vishay-Dale; Power_W: 100mW; TempCo: 100 ppm/C; Value: 191k; EIA_Code: E96; SizeX_mm: 1.6; SizeY_mm: 0.8; SizeZ_mm: 1; Value2: 0.1W; SizeArea_mm2: 1.28; AEC Qualified: Y; VDC_V: 75V; AEC Category: Q200; AEC Grade: 0
R41-R43 = CMP-0021990-4: RES, 100 k, 1%, 0.1 W, AEC-Q200 Grade 0, 0603; Manufacturer: Vishay-Dale; Power_W: 100mW; TempCo: 100 ppm/C; Value: 100k; EIA_Code: E96; SizeX_mm: 1.6; SizeY_mm: 0.8; SizeZ_mm: 1; Value2: 0.1W; SizeArea_mm2: 1.28; AEC Qualified: Y; VDC_V: 75V; AEC Category: Q200; AEC Grade: 0
R46 = CMP-0022443-4: RES, 48.7 k, 1%, 0.1 W, AEC-Q200 Grade 0, 0603; Manufacturer: Vishay-Dale; Power_W: 100mW; TempCo: 100 ppm/C; Value_Code: 48k7; Value: 48.7k; EIA_Code: E96; SizeX_mm: 1.6; SizeY_mm: 0.8; SizeZ_mm: 1; Value2: 0.1W; SizeArea_mm2: 1.28; AEC Qualified: Y; VDC_V: 75V; AEC Category: Q200; AEC Grade: 0
R47 R59 = CMP-0022458-4: RES, 4.99 k, 1%, 0.1 W, AEC-Q200 Grade 0, 0603; Manufacturer: Vishay-Dale; Power_W: 100mW; TempCo: 100 ppm/C; Value_Code: 4k99; Value: 4.99k; EIA_Code: E96; SizeX_mm: 1.6; SizeY_mm: 0.8; SizeZ_mm: 1; Value2: 0.1W; SizeArea_mm2: 1.28; AEC Qualified: Y; VDC_V: 75V; AEC Category: Q200; AEC Grade: 0
R49 = CMP-0022364-4: RES, 38.3 k, 1%, 0.1 W, AEC-Q200 Grade 0, 0603; Manufacturer: Vishay-Dale; Power_W: 100mW; TempCo: 100 ppm/C; Value_Code: 38k3; Value: 38.3k; EIA_Code: E96; SizeX_mm: 1.6; SizeY_mm: 0.8; SizeZ_mm: 1; Value2: 0.1W; SizeArea_mm2: 1.28; AEC Qualified: Y; VDC_V: 75V; AEC Category: Q200; AEC Grade: 0
RT1 RT2 = CMP-0123120-1: Automotive ±1% tolerance 10kΩ linear thermistor available in an 0402 package option 2-SOT-5X3 -40 to 150; Manufacturer: Texas Instruments; SizeZ_mm: 0.77mm; AEC Grade: Grade 0; AEC Qualified: Yes; Max Current: 400uA; TaMax_C: +150°C; TaMin_C: -40°C; TempCo: 6400ppm/°C; TJmax_C: +155°C; VDC_V: 5.5V
U1 U3 = CMP-0121493-2: 100-V, 53-A GaN Half-Bridge Power Stage; Manufacturer: Texas Instruments; SizeZ_mm: 0.85mm; AEC Qualified: No; Max Supply Voltage: 5.25V; Min Supply Voltage: 4.75V; Nominal Supply Current: 12mA; Number Of Drivers: 2; Number Of Outputs: 1; Propagation Delay: 29.5ns; Standoff Height: 0mm; TJmax_C: +150°C; AEC Category: Q200; CompType: IC
U2 = CMP-0122321-1: Automotive, 4-V to 80-V, Functional Safety-Compliant, Dual Synchronous Buck Controller With Low IQ; Manufacturer: Texas Instruments; SizeZ_mm: 1mm; AEC Qualified: Yes; AEC Grade: Grade 1; Max Duty Cycle: 100%; Max Supply Voltage: 80V; Min Supply Voltage: 4V; Nominal Supply Current: 130uA; Number Of Outputs: 2; Output Type: AdjustableProgrammable; Output Voltage: 0.8-60V; Standoff Height: 0mm; Switching Frequency: 100-2200kHz; TaMax_C: +150°C; TaMin_C: -40°C
VIN1 VOUT_BODE VOUT_PWR1 = CMP-0055147-1: Test Point, Multipurpose, Red, TH; Manufacturer: Keystone; CNHeader: FALSE; Green_Lifecycle: Active; Green_REACh: Passed; ContactFinish: Silver; CT: TRUE

## Sheet PMP23591.DynamicLoad.SchDoc
size 431 x 279 mm; Date: Not shown in title block; ApprovedBy: Not shown in title block; CheckedBy: Not shown in title block; Author: Not shown in title block; CompanyName: Not shown in title block; Engineer: Not shown in title block; Organization: Not shown in title block; Address1: Not shown in title block; Address2: Not shown in title block; Address3: Not shown in title block; Address4: Not shown in title block; DocumentNumber: 2; Revision: Use project parameter SCH_Rev; SheetNumber: 2; SheetTotal: 3; PageSetup: Record=PageOptions¦CenterHorizontal=True¦CenterVertical=True¦PrintScale=1.00¦XCorrection=1.00¦YCorrection=1.00¦PrintKind=0¦BorderSize=5000000¦LeftOffset=0¦BottomOffset=0¦Orientation=2¦PaperLength=1000¦PaperWidth=1000¦Scale=100¦PaperSource=15¦PrintQuality=600¦MediaType=1¦DitherType=10¦PaperKind=Letter¦PrintScaleMode=1
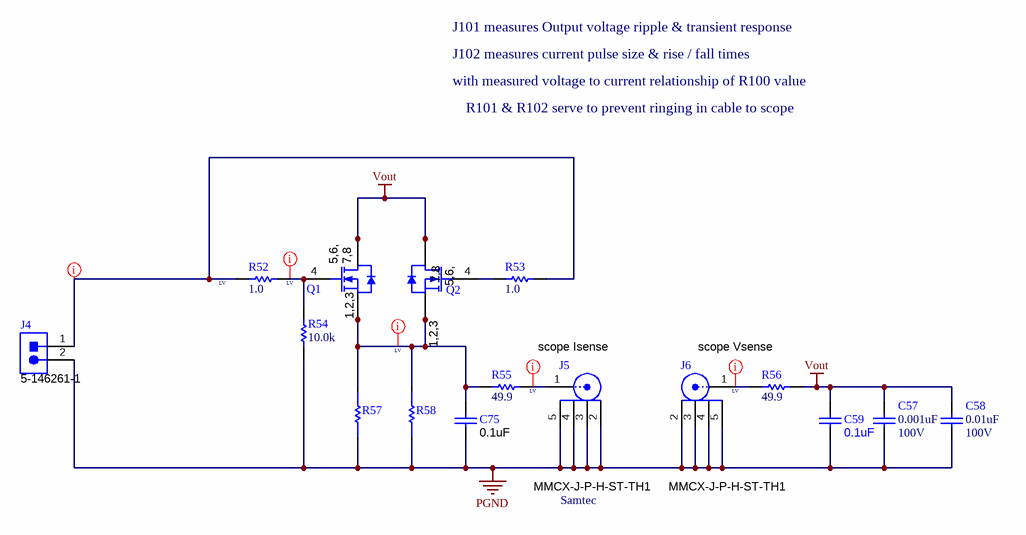
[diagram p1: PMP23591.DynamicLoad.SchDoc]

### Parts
C57  Cap_F: 0.001uF  VDC_V: 100V  [0603]  (hidden comment: CGA3E2X7R2A102K080AA)
C58  Value2: 100V  ValueDisplayed: 0.01uF  [0603]  (hidden comment: GRM188R72A103KA01D)
C59  ValueDisplayed: 0.1uF  [0603]  (hidden comment: CGA3E2X7R1E104K080AA)
C75  ValueDisplayed: 0.1uF  [0603]  (hidden comment: CGA3E2X7R1E104K080AA)
J4  5-146261-1  [CONN_5-146261-1]
J5  MMCX-J-P-H-ST-TH1  Manufacturer: Samtec  [Samtec_MMCX-J-P-H-ST-TH1]
J6  MMCX-J-P-H-ST-TH1  [Samtec_MMCX-J-P-H-ST-TH1]
Q1  CSD17570Q5B  [DNK0008A]  (value not drawn)
Q2  CSD17570Q5B  [DNK0008A]  (value not drawn)
R52  ValueDisplayed: 1.0  [0603]  (hidden comment: CRCW06031R00JNEA)
R53  ValueDisplayed: 1.0  [0603]  (hidden comment: CRCW06031R00JNEA)
R54  ValueDisplayed: 10.0k  [0603]  (hidden comment: CRCW060310K0FKEA)
R55  ValueDisplayed: 49.9  [0603]  (hidden comment: CRCW060349R9FKEA)
R56  ValueDisplayed: 49.9  [0603]  (hidden comment: CRCW060349R9FKEA)
R57  WK73S3ATTER200F  [FP-WK73S3ATTER200F_1225-MFG]  (value not drawn)
R58  WK73S3ATTER200F  [FP-WK73S3ATTER200F_1225-MFG]  (value not drawn)

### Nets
PGND: C57.2 C58.1 C59.1 C75.1 J4.2 J5.2 J5.3 J5.4 J5.5 J6.2 J6.3 J6.4 J6.5 R54.1 R57.1 R58.1
Vout: C57.1 C58.2 C59.2 Q1.5(D) Q1.6(D) Q1.7(D) Q1.8(D) Q1.9(D) Q2.5(D) Q2.6(D) Q2.7(D) Q2.8(D) Q2.9(D) R56.2
NetC75_2: C75.2 Q1.1(S) Q1.2(S) Q1.3(S) Q2.1(S) Q2.2(S) Q2.3(S) R55.1 R57.2 R58.2
NetJ4_1: J4.1 R52.2 R53.1
NetJ5_1: J5.1 R55.2
NetJ6_1: J6.1 R56.1
NetQ1_4: Q1.4(G) R52.1 R54.2
NetQ2_4: Q2.4(G) R53.2

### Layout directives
net class LV: NetC75_2, NetJ4_1, NetJ5_1, NetJ6_1, NetQ1_4

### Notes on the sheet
- J101 measures Output voltage ripple & transient response
- J102 measures current pulse size & rise / fall times
- with measured voltage to current relationship of R100 value
- R101 & R102 serve to prevent ringing in cable to scope
- scope Isense
- scope Vsense

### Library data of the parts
C57 = CMP-0007081-4: as C2 on sheet PMP23591
C58 = CMP-0007468-5: as C3 on sheet PMP23591
C59 C75 = CMP-0007077-5: as C24 on sheet PMP23591
J4 = CMP-0054947-1: Header, 100mil, 2x1, Gold, TH; Manufacturer: TE Connectivity; Green_Lifecycle: Active; Green_REACh: Passed; CNHeader: TRUE; CT: FALSE
J5 = CMP-0075554-1: Connector, MMCX 50 ohm, TH; CT: False; Gender: Female
J6 = CMP-0075554-1: Connector, MMCX 50 ohm, TH; Manufacturer: Samtec; CT: False; Gender: Female
Q1 Q2 = CMP-0000584-2: MOSFET, N-CH, 30 V, 51 A, DNK0008A (VSON-CLIP-8); Alternate Manufacturer: None; Manufacturer: Texas Instruments; SizeZ_mm: 1; ChType: N; Value2: 97 nC; Value1: 0.007; VdsMax_V: 30V; SizeX_mm: 6; SizeAreaWB_mm2: 56; SizeY_mm: 5; Vgs_V: 20V; QgTyp_nC: 97; Value: 30V; Rdson45_ohm: 7.6m; SizeArea_mm2: 30; AEC Category: Q101; IdsMax_A: 51A; U/M: EA
R52 R53 = CMP-0025743-4: RES, 1.0, 5%, 0.1 W, AEC-Q200 Grade 0, 0603; Manufacturer: Vishay-Dale; Power_W: 100mW; TempCo: 200 ppm/C; Value_Code: 1R00; Value: 1.0; EIA_Code: E24; Res_ohm: 1; SizeX_mm: 1.6; SizeY_mm: 0.8; Value2: 0.1W; SizeArea_mm2: 1.28; AEC Qualified: Y; VDC_V: 75V; AEC Category: Q200; AEC Grade: 0
R54 = CMP-0021998-4: as R16 on sheet PMP23591
R55 R56 = CMP-0022448-4: RES, 49.9, 1%, 0.1 W, AEC-Q200 Grade 0, 0603; Manufacturer: Vishay-Dale; Power_W: 100mW; TempCo: 100 ppm/C; Value_Code: 49R9; Value: 49.9; EIA_Code: E96; SizeX_mm: 1.6; SizeY_mm: 0.8; SizeZ_mm: 1; Value2: 0.1W; SizeArea_mm2: 1.28; AEC Qualified: Y; VDC_V: 75V; AEC Category: Q200; AEC Grade: 0
R57 R58 = CMP-0124591-1: 200 mOhms ±1% 1.5W Chip Resistor Wide 2512 (6432 Metric), 1225 Automotive AEC-Q200, Moisture Resistant Thick Film; Manufacturer: KOA Speer; AEC Grade: Grade 0; AEC Qualified: Yes; Res_ohm: 0.2; SizeZ_mm: 0.7mm; TempCo: 200ppm/°C; Value: 0.2

## Sheet PMP23591_Hardware.SchDoc
size 431 x 279 mm; Date: Not shown in title block; ApprovedBy: Not shown in title block; CheckedBy: Not shown in title block; Author: Not shown in title block; CompanyName: Not shown in title block; Engineer: Not shown in title block; Organization: Not shown in title block; Address1: Not shown in title block; Address2: Not shown in title block; Address3: Not shown in title block; Address4: Not shown in title block; DocumentNumber: 3; Revision: Use project parameter SCH_Rev; SheetNumber: 3; SheetTotal: 3; PageSetup: Record=PageOptions¦CenterHorizontal=True¦CenterVertical=True¦PrintScale=1.00¦XCorrection=1.00¦YCorrection=1.00¦PrintKind=0¦BorderSize=5000000¦LeftOffset=0¦BottomOffset=0¦Orientation=2¦PaperLength=1000¦PaperWidth=1000¦Scale=100¦PaperSource=15¦PrintQuality=600¦MediaType=1¦DitherType=10¦PaperKind=Letter¦PrintScaleMode=1
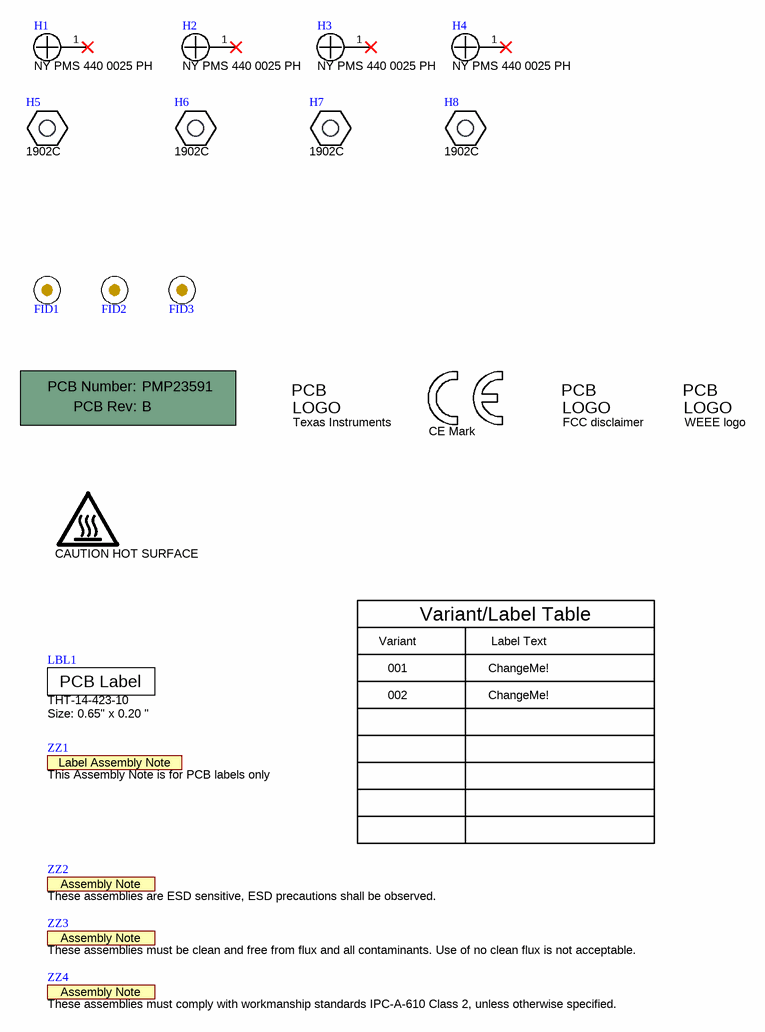
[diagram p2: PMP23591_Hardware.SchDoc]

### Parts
!PCB1  Printed Circuit Board  (value not drawn)  (mechanical)
CAUTION_HOT_SURFACE1  CAUTION HOT SURFACE  [IEC_HotSurface_Small]  (no BOM)
FID1  Fiducial  [Fiducial10-20]  (value not drawn)
FID2  Fiducial  [Fiducial10-20]  (value not drawn)
FID3  Fiducial  [Fiducial10-20]  (value not drawn)
H1  NY PMS 440 0025 PH  [NY PMS 440 0025 PH]
H2  NY PMS 440 0025 PH  [NY PMS 440 0025 PH]
H3  NY PMS 440 0025 PH  [NY PMS 440 0025 PH]
H4  NY PMS 440 0025 PH  [NY PMS 440 0025 PH]
H5  1902C  [Keystone_1902C]
H6  1902C  [Keystone_1902C]
H7  1902C  [Keystone_1902C]
H8  1902C  [Keystone_1902C]
LBL1  THT-14-423-10  Note: Size: 0.65" x 0.20 "  [Label_650x200]
Logo1  CE Mark  [CE_Mark_5mm]  (no BOM)
Logo2  Texas Instruments  [TI_Stacked_Overlay_Small]  (no BOM)
Logo3  FCC disclaimer  [FCC_disclaimer]  (no BOM)
Logo4  WEEE logo  [WEEE_Minimum]  (no BOM)
ZZ1  This Assembly Note is for PCB labels only  [AssemblyNoteLabel]  (no BOM)
ZZ2  These assemblies are ESD sensitive, ESD precautions shall be observed.  [AssemblyNote]  (no BOM)
ZZ3  These assemblies must be clean and free from flux and all contaminants. Use of no clean flux is not acceptable.  [AssemblyNote]  (no BOM)
ZZ4  These assemblies must comply with workmanship standards IPC-A-610 Class 2, unless otherwise specified.  [AssemblyNote]  (no BOM)

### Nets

Not connected (* = marked no-connect by the designer): H1 1*; H2 1*; H3 1*; H4 1*

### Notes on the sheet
- Variant
- Variant/Label Table
- Label Text
- 001
- 002
- ChangeMe!

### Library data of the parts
!PCB1 = CMP-0003618-2: Manufacturer: Any; PartNumber: PMP23591
CAUTION_HOT_SURFACE1 = CMP-0074837-2: IEC 61010-1 Hot Surface Warning; Manufacturer: Texas Instruments; SymbolCreator: a0412235; CompType: IC; AEC Category: Q200
FID1-FID3 = CMP-0077181-1: Fiducial mark.  There is nothing to buy or mount.
H1-H4 = CMP-0003617-1: Machine Screw, Round, #4-40 x 1/4, Nylon, Philips panhead; Manufacturer: B&F Fastener Supply; CompType: Hardware
H5-H8 = CMP-0003610-1: Standoff, Hex, 0.5"L #4-40 Nylon; Manufacturer: Keystone; CompType: Hardware
LBL1 = CMP-0003625-1: Thermal Transfer Printable Labels, 0.650" W x 0.200" H - 10,000 per roll; Manufacturer: Brady; CompType: Label
Logo1 = CMP-0074844-1: SymbolCreator: a0412235
Logo2 = CMP-0074838-1: Texas Instrument Corporate Signature; SymbolCreator: a0412235; Lib Reference: TI_Logo; Library Reference: Logo
Logo3 = CMP-0074847-1: FCC_disclaimer; Library Reference: Logo
Logo4 = CMP-0074769-1
ZZ1 = CMP-0003616-3
ZZ2 = CMP-0077236-1
ZZ3 = CMP-0077237-1
ZZ4 = CMP-0077238-1

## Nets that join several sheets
PGND: PMP23591 (73 pins), PMP23591.DynamicLoad (16 pins)
Vout: PMP23591 (35 pins), PMP23591.DynamicLoad (14 pins)

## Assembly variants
001: not fitted C15 C16 C17 C35 C36 C65 C66 C67 FID1 FID2 FID3 R5 R6 R7 R8 R11 R14 R15 R29 R30 R31 R32 R34 R38 R39 R46 R60 R61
